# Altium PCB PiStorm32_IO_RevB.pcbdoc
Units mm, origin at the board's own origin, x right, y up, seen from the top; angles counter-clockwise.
Board outline 55 x 107.5 mm, 2 copper layers (Top Layer, Bottom Layer), stack 1.569 mm thick; 30 components, 37 nets, 213 pads, 281 vias.
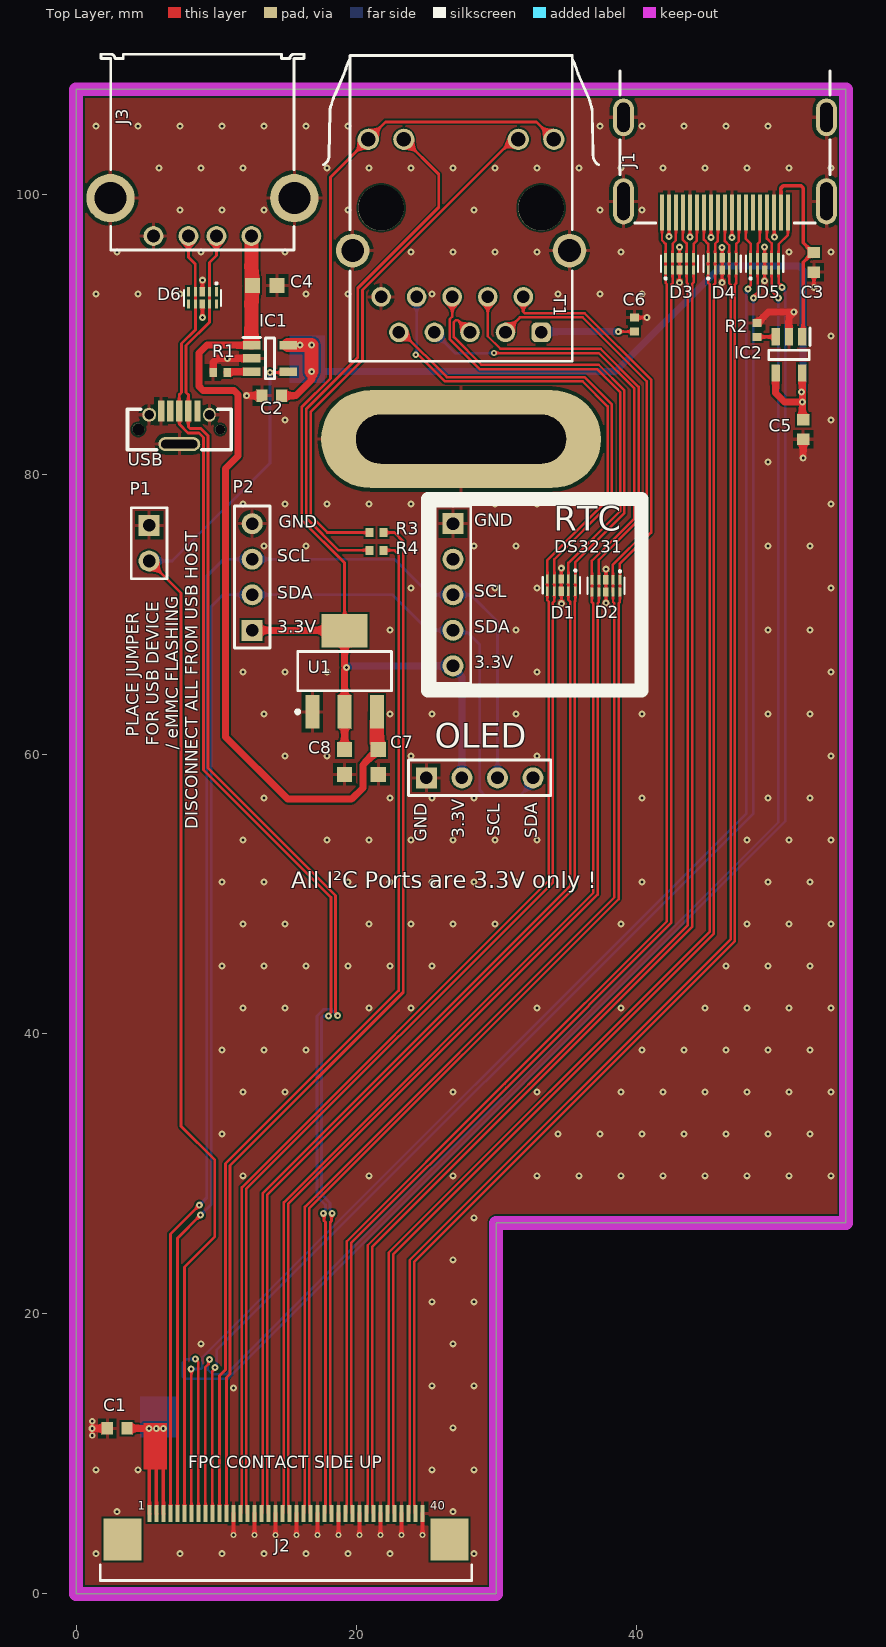
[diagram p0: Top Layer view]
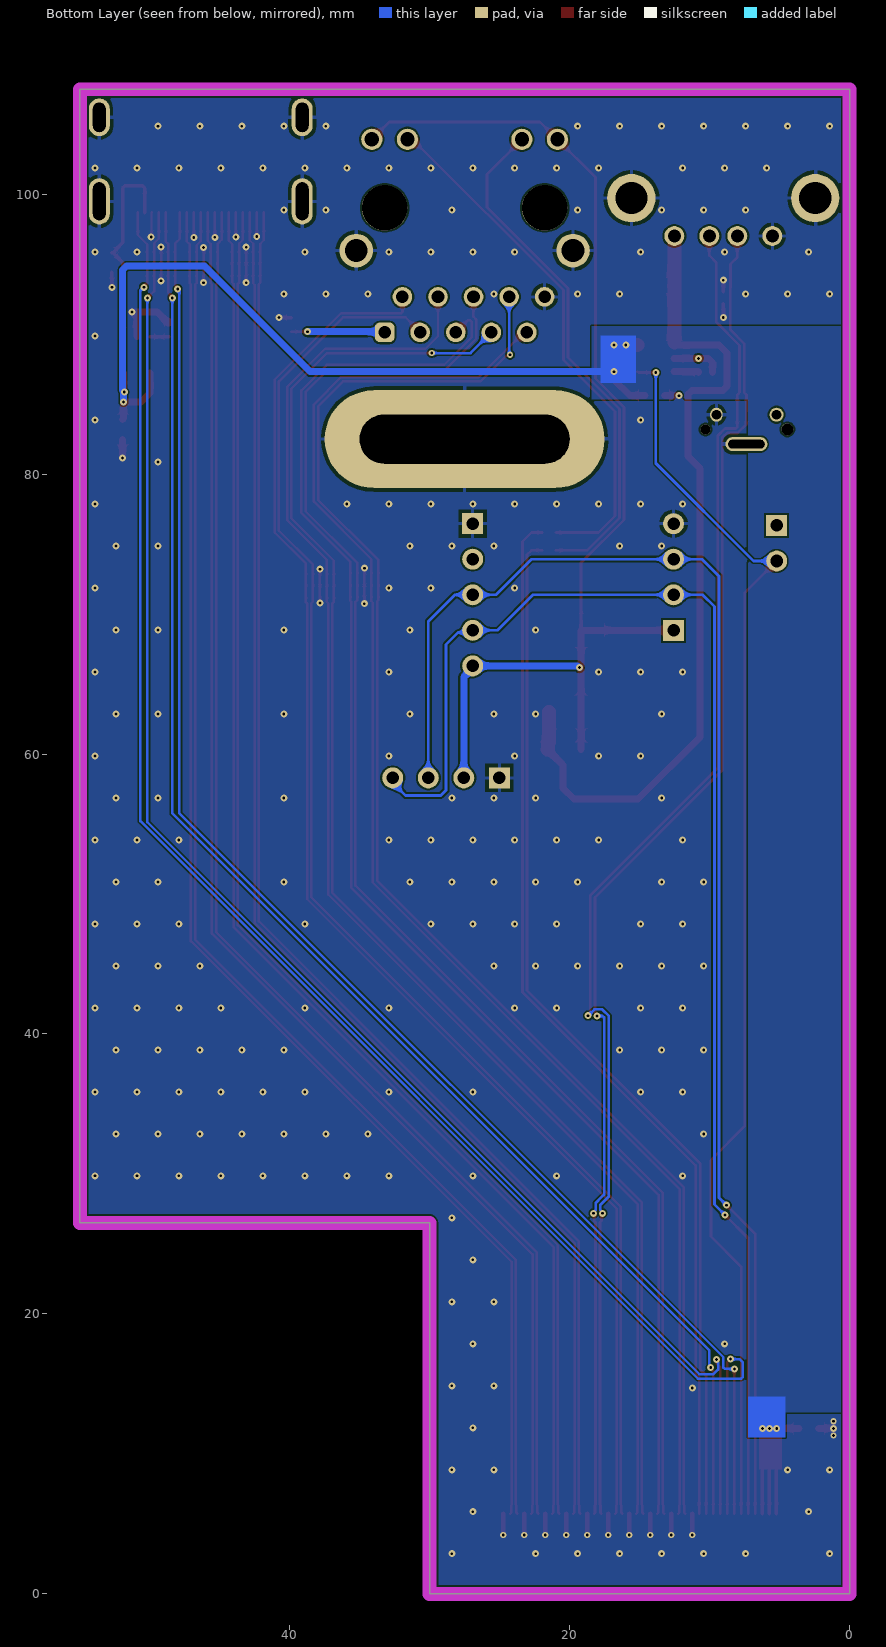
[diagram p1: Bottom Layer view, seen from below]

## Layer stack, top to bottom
Top Solder: solder mask 0.0254, SM-001, Dk 4
Top Layer: signal copper 0.035
Dielectric 1: core 1.4986, Core-043, Dk 4.3
Bottom Layer: signal copper 0.035
Bottom Solder: solder mask 0.0254, SM-001, Dk 4

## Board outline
0,0 0,107.5 55,107.5 55,26.5 30,26.5 30,0

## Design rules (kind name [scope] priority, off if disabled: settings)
Clearance [All] p1: gap=0.127 ignorepadtopadclearanceinfootprint=FALSE
DiffPairsRouting [All] p1: maxlimit=0.254 minlimit=0.127 mostfreqgap=0.127 toplayer_minwidth=0.127 toplayer_maxwidth=0.381 toplayer_prefwidth=0.127 bottomlayer_minwidth=0.127 bottomlayer_maxwidth=0.381 bottomlayer_prefwidth=0.127 maxuncoupledlength=12.7
PolygonConnect [All] p1: thpad.connectstyle=Relief thpad.reliefconductorwidth=0.254 thpad.reliefentries=4 thpad.polygonreliefangle="90 Angle" thpad.airgapwidth=0.254 smdpad.connectstyle=Relief smdpad.reliefconductorwidth=0.254 smdpad.reliefentries=4 smdpad.polygonreliefangle="90 Angle" smdpad.airgapwidth=0.254 via.connectstyle=Direct via.reliefconductorwidth=0.254 via.reliefentries=4 via.polygonreliefangle="90 Angle" via.airgapwidth=0.254
RoutingVias [All] p1: holewidth=0.2 width=0.5 viastyle="Through Hole" minholewidth=0.2 minwidth=0.5 maxholewidth=0.6 maxwidth=1
SolderMaskExpansion [All] p1: expansion=0.102 istentingtop=FALSE
UnRoutedNet [All] p1: checkbadconnections=TRUE
Width [All] p1: maxlimit=4 minlimit=0.178 preferedwidth=0.254
28 further rules are at their usual default settings.

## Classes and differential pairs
differential pair USB: +USB_P -USB_N
differential pair HDMI_TX2: +HDMI_TX2_P -HDMI_TX2_N
differential pair HDMI_TX1: +HDMI_TX1_P -HDMI_TX1_N
differential pair HDMI_TX0: +HDMI_TX0_P -HDMI_TX0_N
differential pair HDMI_CLK: +HDMI_CLK_P -HDMI_CLK_N
differential pair ETH_P3: +ETH_P3_P -ETH_P3_N
differential pair ETH_P2: +ETH_P2_P -ETH_P2_N
differential pair ETH_P1: +ETH_P1_P -ETH_P1_N
differential pair ETH_P0: +ETH_P0_P -ETH_P0_N

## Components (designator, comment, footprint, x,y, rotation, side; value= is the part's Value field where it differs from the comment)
C1 "Cap Semi" 1608[0603] 2.921,11.818 r180 top value=2u2
C2 "Cap Semi" 1608[0603] 13.97,85.605 r180 top value=2u2
C3 "Cap Semi" 1608[0603] 52.705,95.13 r270 top value=2u2
C4 "Cap Semi" RCL_C0603K 13.462,93.479 r0 top value=22uf/0603
C5 "Cap Semi" 1608[0603] 51.943,83.192 r270 top value=2u2
C6 "100nf/0402" 005-00008 39.878,90.685 r270 top value=1uF
C7 "Cap Semi" RCL_C0603K 21.59,59.443 r270 top value=22uf/0603
C8 "Cap Semi" RCL_C0603K 19.177,59.443 r270 top value=22uf/0603
D1 "ESD5304D-TP" DFN2510-10_L2.5-W1.0-P0.50-BL 34.663,72.068 r180 top
D2 "ESD5304D-TP" DFN2510-10_L2.5-W1.0-P0.50-BL 37.846,72.016 r180 top
D3 "ESD5304D-TP" DFN2510-10_L2.5-W1.0-P0.50-BL 43.108,95.023 r0 top
D4 "ESD5304D-TP" DFN2510-10_L2.5-W1.0-P0.50-BL 46.156,95.023 r0 top
D5 "ESD5304D-TP" DFN2510-10_L2.5-W1.0-P0.50-BL 49.188,95.023 r0 top
D6 "ESD5304D-TP" DFN2510-10_L2.5-W1.0-P0.50-BL 9.017,92.59 r180 top
IC1 "MT9700" SOT95P280X135-5N 13.843,88.272 r0 top
IC2 "MT9700" SOT95P280X135-5N 50.927,88.526 r270 top
J1 "C138388" 685119134923 46.355,104.02 r180 top
J2 "68714014022" 68714014022 14.986,3.175 r0 top
J3 "C112456" 61400416021 9.017,103.004 r180 top
OLED "Header 4" HDR1X4 25.019,58.3 r0 top
P1 "Header 2" HDR1X2 5.207,76.334 r270 top
P2 "Header 4" HDR1X4 12.573,68.841 r90 top
R1 "5.6k" 005-00008 10.287,87.256 r0 top value=22
R2 "12k" 005-00008 48.641,90.304 r270 top value=22
R3 "470" 005-00008 21.463,75.826 r180 top value=22
R4 "470" 005-00008 21.463,74.556 r180 top value=22
RTC "Header 5" HDR1X5 26.924,76.461 r270 top
T1 "HY911130A" HY911130A 27.5,99.021 r0 top
U1 "LM1117IMPX-3.3" MP04A_N 19.177,65.92 r90 top
USB "U-E-051N-4BH21-F1B" MICRO-USB-SMD_U-E-051N-4BH21-F1B 7.366,83.319 r180 top

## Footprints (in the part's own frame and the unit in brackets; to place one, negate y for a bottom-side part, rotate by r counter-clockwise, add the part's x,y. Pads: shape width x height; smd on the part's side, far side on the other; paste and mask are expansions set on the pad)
005-00008 [mm] "1005, EIA 0402, Chip Capacitor, 2-Leads, Body 1.00x0.50mm, IPC High Density"
  rect 0.55x0.65 smd: 1(-0.5,0) 2(0.5,0)
  body extent -0.52,-0.27 0.53,0.28, height 0.4
1608[0603] [mm] "Chip Capacitor, Body 1.6x0.8mm, IPC High Density"
  rect 0.8x0.9 smd: 1(-0.7,0) 2(0.7,0)
  body extent -0.87,-0.48 0.87,0.48, height 1.3
61400416021 [mm] "USB 2.0 Type A Horizontal"
  round 1.42 hole 0.92: 1(-3.5,5.99) 2(-1,5.99) 3(1,5.99) 4(3.5,5.99)
  round 3.45 hole 2.3: Shell(-6.57,3.28) Shell(6.57,3.28)
  silkscreen extent -7.25,-7 7.25,7, body extent -8,-7 8,7, height 7.63
68714014022 [mm] "ZIF Connectors, Horizontal, Top Contact, pitch 0.5mm, 40p"
  rect 0.3x1.2 smd: 1(-9.75,2.56) 2(-9.25,2.56) 3(-8.75,2.56) 4(-8.25,2.56) 5(-7.75,2.56) 6(-7.25,2.56) 7(-6.75,2.56) 8(-6.25,2.56) 9(-5.75,2.56) 10(-5.25,2.56) 11(-4.75,2.56) 12(-4.25,2.56) 13(-3.75,2.56) 14(-3.25,2.56) 15(-2.75,2.56) 16(-2.25,2.56) 17(-1.75,2.56) 18(-1.25,2.56) 19(-0.75,2.56) 20(-0.25,2.56) 21(0.25,2.56) 22(0.75,2.56) 23(1.25,2.56) 24(1.75,2.56) 25(2.25,2.56) 26(2.75,2.56) 27(3.25,2.56) 28(3.75,2.56) 29(4.25,2.56) 30(4.75,2.56) 31(5.25,2.56) 32(5.75,2.56) 33(6.25,2.56) 34(6.75,2.56) 35(7.25,2.56) 36(7.75,2.56) 37(8.25,2.56) 38(8.75,2.56) 39(9.25,2.56) 40(9.75,2.56)
  rect 2.7x3 smd: MP1(-11.68,0.7) MP2(11.68,0.7)
  silkscreen extent -13.27,-2.23 13.28,-1.1, body extent -13.2,-2.15 13.2,2.95, height 2.1
685119134923 [mm] "HDMI SMT Horizontal"
  rect 0.28x2.6 smd: 1(4.5,5.325) 2(4,5.325) 3(3.5,5.325) 4(3,5.325) 5(2.5,5.325) 6(2,5.325) 7(1.5,5.325) 8(1,5.325) 9(0.5,5.325) 10(0,5.325) 11(-0.5,5.325) 12(-1,5.325) 13(-1.5,5.325) 14(-2,5.325) 15(-2.5,5.325) 16(-3,5.325) 17(-3.5,5.325) 18(-4,5.325) 19(-4.5,5.325)
  oval 1.5x3.3 hole 0.9 slot 2.7 at 90 deg: Shell(-7.25,4.525) Shell(7.25,4.525)
  oval 1.5x2.7 hole 0.9 slot 2.1 at 90 deg: Shell(-7.25,-1.475) Shell(7.25,-1.475)
  silkscreen extent -7.5,-4.78 7.5,6.08, body extent -7.55,-6.07 7.45,6.08, height 6.17
DFN2510-10_L2.5-W1.0-P0.50-BL [mm]
  rect 0.2x0.665 smd: 1(-1,-0.433) 2(-0.5,-0.433) 4(0.5,-0.433) 5(1,-0.433) 6(1,0.433) 7(0.5,0.433) 9(-0.5,0.433) 10(-1,0.433)
  rect 0.4x0.665 smd: 3(0,-0.433) 8(0,0.433)
  silkscreen extent -1.33,-1.11 1.33,0.58
HDR1X2 [mm] "Connector; Header; 2 Position"
  rect 1.5x1.5 hole 0.9: 1(0,0)
  round 1.5 hole 0.9: 2(2.54,0)
  silkscreen extent -1.27,-1.27 3.81,1.27
HDR1X4 [mm] "Connector; Header; 4 Position"
  rect 1.5x1.5 hole 0.9: 1(0,0)
  round 1.5 hole 0.9: 2(2.54,0) 3(5.08,0) 4(7.62,0)
  silkscreen extent -1.27,-1.27 8.89,1.27
HDR1X5 [mm] "Connector; Header; 5 Position"
  rect 1.5x1.5 hole 0.9: 1(0,0)
  round 1.5 hole 0.9: 2(2.54,0) 3(5.08,0) 4(7.62,0) 5(10.16,0)
  silkscreen extent -1.27,-1.27 11.43,1.27
HY911130A [mm] "LAN Transformer, body 21.84x15.88mm"
  rrect50% 1.4x1.4 hole 0.9: 1(5.715,-8.89)
  round 1.4 hole 0.9: 2(4.445,-6.35) 3(3.175,-8.89) 4(1.905,-6.35) 5(0.635,-8.89) 6(-0.635,-6.35) 7(-1.905,-8.89) 8(-3.175,-6.35) 9(-4.445,-8.89) 10(-5.715,-6.35)
  round 1.52 hole 1.02: 11(6.63,4.9) 12(4.09,4.9) 13(-4.09,4.9) 14(-6.63,4.9)
  round 3.25 hole 3.25 unplated: MH1(5.715,0) MH2(-5.715,0)
  round 2.4 hole 1.63: Shell(-7.745,-3.05) Shell(7.745,-3.05)
  silkscreen extent -9.83,-10.95 9.83,10.89, body extent -9.92,-10.95 9.92,10.89, height 16.01
MICRO-USB-SMD_U-E-051N-4BH21-F1B [mm]
  rect 0.45x1.5 smd: 1(-1.3,-1.175) 2(-0.65,-1.175) 3(0,-1.175) 4(0.65,-1.175) 5(1.3,-1.175)
  oval 0.9x1 hole 0.7: 6(-2.15,-0.925)
  round 1 hole 0.7: 7(2.15,-0.925)
  oval 3x1 hole 0.6 slot 2.6 at 0 deg: 8(0,1.175)
  round 0.7 hole 0.7 unplated: ""(-2.925,0.125)
  round 0.85 hole 0.85 unplated: ""(2.925,0.125)
  silkscreen extent -3.7,-1.33 3.7,1.57
MP04A_N [mm] "SOT223, 4-Leads, Body 6.5x3.5mm, Pitch 2.3mm, Lead Span 7mm, IPC Medium Density"
  rect 2.4x1 smd: 1(-2.9,2.3) 2(-2.9,0) 3(-2.9,-2.3)
  rect 2.4x3.3 smd: 4(2.9,0)
  silkscreen extent -3.02,-3.35 1.4,3.47, body extent -1.85,-3.35 1.85,3.35, height 1.8
RCL_C0603K [mil]
  rect 42x43 smd: 1(-34.45,0) 2(35,0)
SOT95P280X135-5N [mm]
  rect 1.25x0.6 smd: 1(-1.3,0.95) 2(-1.3,0) 3(-1.3,-0.95) 4(1.3,-0.95) 5(1.3,0.95)
  silkscreen extent -1.92,-1.45 0.33,1.5, body extent -1.4,-1.45 1.4,1.45, height 1.35

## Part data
C1 C2 C3 C4 C5 C7 C8: "Capacitor (Semiconductor SIM Model)"
C6: library part 004-00003, "Capacitor 1uF 10V Ceramic 10% 0402", Manufacturer1=AVX, Manufacturer1 Part Number=0402ZD105KAT2A, Package="1005, EIA 0402, Chip Capacitor, 2-Leads, Body 1.00x0.50mm, IPC High Density", Part Number=011-00010, Voltage=10V
D1 D2 D3 D4 D5 D6: BOM_JLCPCB Part Class="Extended Part", BOM_Manufacturer="TECH PUBLIC(台舟)"
IC1 IC2: "Integrated Circuit", Manufacturer_Name=Aerosemi
J1: library part 685119134923, "HDMI Type A Receptacle WR-HDMI, Horizontal, SMT", Contact Resistance="30 mOhm", Operating Temperature="-20 to 85 degC", Rated Current="0.5 A", Working Voltage="40 VDC"
J2: "WR-FPC SMT ZIF Horizontal Top Contact, pitch 0.5mm, 40p", Contact Resistance=20mOhm, Manufacturer="Wurth Elektronik", Operating Temperature="-25 to +85degC", Rated Current=0.5A, Working Voltage=50VAC
J3: library part 61400416021, "USB 2.0 Type A, Receptacle, Horizontal, THT", Manufacturer="Wurth Elektronik", Operating Temperature="-40 to +105degC", Rated Current=1.5A, Working Voltage=30VAC
OLED P2: "Header, 4-Pin"
P1: "Header, 2-Pin"
R1 R2 R3 R4: library part 004-00008, "RES 22 OHM 1/16W 5% 0402", Manufacturer1="Stackpole Electronics", Manufacturer1 Part Number=RMCF0402JT22R0, Package="1005, EIA 0402, Chip Resistor, 2-Leads, Body 1.00x0.50mm, IPC High Density", Part Number=009-00020, Power=1/16W, Tolerance=0.05
RTC: "Header, 5-Pin"
T1: "LAN Transformer, THT, 10/100/1000 Base-T, Port 1x1, Tab Down", Manufacturer="Wurth Elektronik", Manufacturer Part Number=7499111446, Operating Temperature="-40 to +85degC"
U1: "800mA Low-Dropout Linear Regulator, 4-pin SOT-223", Manufacturer="National Semiconductor", PackageTopMarking=XYTT*N05B, PowerWise=N
USB: BOM_JLCPCB Part Class="Extended Part", BOM_Manufacturer="XKB Enterprise"

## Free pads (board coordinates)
  oval 20x7 hole 3.5 slot 15 at 0 deg: MNT(27.5,82.5)

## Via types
v1: diameter 0.5, hole 0.2, Top Layer to Bottom Layer, tented both sides, 267 vias
v2: diameter 0.45, hole 0.2, Top Layer to Bottom Layer, tented both sides, 14 vias

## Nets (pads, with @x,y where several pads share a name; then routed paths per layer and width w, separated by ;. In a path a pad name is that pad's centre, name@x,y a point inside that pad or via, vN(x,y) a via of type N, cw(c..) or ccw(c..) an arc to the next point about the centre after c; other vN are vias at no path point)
+5: C1.1 C2.1 C5.1 IC1.5 IC2.4 IC2.5 J2.1 J2.2 J2.3 | length 81.6
  Top Layer w0.254: J2.1 5.222,5.75 5.222,11.803 v1(5.207,11.818) v1@5.236,11.847 ; v1(5.723,11.818) 5.73,11.811 5.73,5.742 J2.2 ; v1(6.223,11.818) 6.23,11.811 6.23,5.742 J2.3
  Top Layer w0.5: C1.1 v1(5.207,11.818) ; C2.1@14.608,85.605 15.691,85.605 16.825,86.739 v1(16.825,87.322) ; IC2.4 49.977,85.798 50.617,85.158 v1(51.877,85.158) ; IC2.5 51.877,85.92 v1(51.816,85.859) 51.877,85.798 v1(51.877,85.158) ; C5.1 51.877,83.958 v1(51.877,85.158)
  Top Layer w1: IC1.5 v1(15.984,89.222) v1(16.825,89.222) v1(16.825,87.322)
  Bottom Layer w0.5: v1(16.825,87.322) 38.547,87.322 46.101,94.876 51.65,94.876 51.943,94.583 51.943,85.986 v1(51.816,85.859) 51.877,85.798 v1(51.877,85.158)
+5_SW: C4.1 C7.1 IC1.1 J3.1 U1.3 | length 59.8
  Top Layer w0.5: IC1.1 9.332,89.222 8.763,88.653 8.763,86.279 9.056,85.986 11.264,85.986 11.557,85.693 11.557,81.287 10.668,80.398 10.668,61.221 15.113,56.776 19.685,56.776 20.489,57.58 20.489,59.23 21.577,60.318 C7.1
  Top Layer w1: IC1.1@12.517,89.422 12.517,93.396 12.554,93.433 C4.1@12.554,93.479 ; C4.1@12.517,93.479 J3.1 ; U1.3 21.477,62.32 21.463,62.306 21.463,60.817 21.544,60.736 21.544,60.351 C7.1@21.577,60.318
ETH_LNK: J2.12 R3.1 | length 76.4
  Top Layer w0.2: J2.12 10.736,15.442 10.995,15.701 10.995,30.606 23.368,42.979 23.368,75.191 22.733,75.826 R3.1
ETH_P0_N: D2.2 D2.9 J2.23 T1.3 | length 103.5
  Top Layer w0.178: J2.23 16.297,5.796 16.297,6.314 16.334,6.35 16.334,27.644 38.444,49.754 38.444,70.776 38.354,70.866 D2.9@38.354,71.538 ; T1.3@30.675,90.161 31.707,91.193 36.195,91.193 40.767,86.621 40.767,75.953 38.346,73.532 D2.2 D2.9
ETH_P0_P: D2.1 D2.10 J2.24 T1.2 | length 103.4
  Top Layer w0.178: J2.24 16.675,5.796 16.675,6.314 16.638,6.35 16.638,27.517 38.748,49.627 38.748,70.759 38.846,70.857 D2.1 38.846,73.601 41.072,75.827 41.072,86.747 36.321,91.498 32.045,91.498 31.94,91.602 T1.2@31.94,92.696
ETH_P1_N: D2.4 D2.7 J2.21 T1.4 | length 106
  Top Layer w0.178: J2.21 15.175,5.796 15.175,6.314 15.138,6.35 15.138,27.845 37.248,49.955 37.248,70.776 37.346,70.874 D2.7 D2.4 37.338,72.457 37.338,73.871 40.183,76.716 40.183,86.239 37.464,88.958 30.553,88.958 30.302,88.958 29.405,89.855 T1.4
ETH_P1_P: D2.5 D2.6 J2.20 T1.7 | length 106.8
  Top Layer w0.178: J2.20 14.797,5.796 14.797,6.314 14.834,6.35 14.834,27.972 36.944,50.082 36.944,70.759 36.846,70.857 D2.6 D2.5 36.846,73.81 39.878,76.842 39.878,86.113 37.338,88.653 30.427,88.653 v2(29.845,88.653)
  Bottom Layer w0.178: T1.7 27.073,88.653 v2(29.845,88.653)
ETH_P2_N: D1.2 D1.9 J2.17 T1.6 | length 107.6
  Top Layer w0.178: J2.17 13.297,5.796 13.297,6.314 13.334,6.35 13.334,28.631 35.305,50.602 35.305,70.874 35.163,71.016 D1.9 ; T1.6 26.87,92.666 26.87,91.249 26.676,91.056 26.676,89.664 28.83,87.51 37.211,87.51 38.862,85.859 38.862,77.35 35.163,73.651 D1.2 ; D1.9@35.163,71.724 D1.2
ETH_P2_P: D1.1 D1.10 J2.18 T1.5 | length 107.3
  Top Layer w0.178: J2.18 13.675,5.796 13.675,6.314 13.638,6.35 13.638,28.504 35.61,50.476 35.61,70.891 35.663,70.944 D1.10 D1.1 35.663,73.72 39.167,77.224 39.167,85.985 37.337,87.815 28.956,87.815 26.981,89.79 26.981,90.869 27.115,91.003 27.263,91.003 T1.5
ETH_P3_N: D1.4 D1.7 J2.15 T1.9 | length 107.5
  Top Layer w0.178: J2.15 12.175,5.796 12.175,6.314 12.138,6.35 12.138,28.909 34.065,50.836 34.065,70.828 34.163,70.926 D1.7 D1.4 34.163,73.921 38.278,78.036 38.278,84.969 36.321,86.926 26.481,86.926 23.276,90.131 T1.9
ETH_P3_P: D1.5 D1.6 J2.14 T1.8 | length 109.5
  Top Layer w0.178: J2.14 11.797,5.796 11.797,6.314 11.834,6.35 11.834,29.036 33.761,50.963 33.761,70.894 33.663,70.992 D1.6 D1.5 33.663,73.852 37.973,78.162 37.973,84.843 36.195,86.621 26.354,86.621 24.502,88.474 24.309,88.474 v2(24.257,88.526)
  Bottom Layer w0.178: v2(24.257,88.526) 24.257,88.6 24.325,88.668 T1.8
ETH_SPD: J2.11 R4.1 | length 75
  Top Layer w0.2: J2.11 10.236,15.577 10.668,16.009 10.668,30.741 23.041,43.114 23.041,74.248 22.733,74.556 R4.1
GND: C1.2 C2.2 C3.2 C4.2 C5.2 C6.1 C7.2 C8.2 D1.3 D1.8 D2.3 D2.8 D3.3 D3.8 D4.3 D4.8 D5.3 D5.8 D6.3 D6.8 IC1.2 IC2.2 J1.2 J1.5 J1.8 J1.11 J1.17 J1.Shell J2.13 J2.16 J2.19 J2.22 J2.25 J2.28 J2.31 J2.34 J2.37 J2.40 J3.4 J3.Shell OLED.1 P1.1 P2.4 pad.MNT R1.1 R2.1 RTC.1 T1.10 T1.Shell U1.1 USB.5 USB.6 USB.7 USB.8 | length 53.3
  Top Layer w0.178: v1(34.671,70.746) 34.663,70.754 D1.8 v1(34.663,73.278) v1@34.671,73.286 ; v1(37.846,70.798) D2.8 D2.3 v1(37.846,73.211) ; v1(42.355,96.972) J1.2 ; v1(43.108,93.678) D3.8 v1(43.108,96.218) ; v1(43.855,96.948) J1.5 ; v1(45.355,96.924) J1.8 ; v1(46.153,96.198) 46.154,96.196 46.154,95.458 D4.8 v1(46.156,93.678) ; v1(46.855,96.916) J1.11 ; v1(49.188,96.234) D5.8 D5.3 49.188,93.821 v1(49.196,93.813) v1@49.204,93.805 ; J1.17 49.875,98.675 49.875,96.968 v1(49.895,96.948)
  Top Layer w0.254: v1(9.017,91.193) D6.8 ; D6.3 v1(9.017,93.86) ; C6.1 40.759,91.185 v1(40.767,91.193) ; v1(52.705,93.352) C3.2
  Top Layer w0.3: v2(1.143,11.31) v2(1.143,12.326) ; v2(11.236,4.198) J2.13 ; v2(12.736,4.198) J2.16 ; v2(14.236,4.198) J2.19 ; v2(15.736,4.198) J2.22 ; v2(17.236,4.198) J2.25 ; v2(18.736,4.198) J2.28 ; v2(20.236,4.198) J2.31 ; v2(21.736,4.198) J2.34 ; v2(23.236,4.198) J2.37 ; v2(24.736,4.198) J2.40
  Top Layer w0.5: v1(1.143,11.818) C1.2 ; R1.1 9.787,87.979 10.08,88.272 v1(10.795,88.272) IC1.2 ; v1(12.184,85.605) C2.2@13.208,85.605 ; R2.1 48.691,90.804 49.461,91.574 v1(51.275,91.574) 51.308,91.574 50.927,91.193 IC2.2 ; v1(51.943,81.16) C5.2
  other v1: 1.421,2.863 7.421,2.863 10.421,2.863 13.421,2.863 16.421,2.863 19.421,2.863 22.421,2.863 28.421,2.863 2.921,5.863 26.921,5.863 1.421,8.863 4.421,8.863 25.421,8.863 28.421,8.863 26.921,11.863 11.236,14.705 25.421,14.863 28.421,14.863 8.921,17.863 26.921,17.863 25.421,20.863 28.421,20.863 26.921,23.863 28.421,26.863 11.921,29.863 20.921,29.863 26.921,29.863 32.921,29.863 35.921,29.863 38.921,29.863 41.921,29.863 44.921,29.863 47.921,29.863 50.921,29.863 53.921,29.863 10.421,32.863 34.421,32.863 37.421,32.863 40.421,32.863 43.421,32.863 46.421,32.863 49.421,32.863 52.421,32.863 11.921,35.863 14.921,35.863 26.921,35.863 32.921,35.863 38.921,35.863 41.921,35.863 44.921,35.863 47.921,35.863 50.921,35.863 53.921,35.863 10.421,38.863 13.421,38.863 16.421,38.863 40.421,38.863 43.421,38.863 46.421,38.863 49.421,38.863 52.421,38.863 11.921,41.863 14.921,41.863 20.921,41.863 23.921,41.863 32.921,41.863 38.921,41.863 44.921,41.863 47.921,41.863 50.921,41.863 53.921,41.863 10.421,44.863 13.421,44.863 16.421,44.863 19.421,44.863 22.421,44.863 25.421,44.863 46.421,44.863 49.421,44.863 52.421,44.863 11.921,47.863 14.921,47.863 20.921,47.863 23.921,47.863 26.921,47.863 29.921,47.863 38.921,47.863 47.921,47.863 50.921,47.863 53.921,47.863 10.421,50.863 13.421,50.863 19.421,50.863 22.421,50.863 25.421,50.863 28.421,50.863 31.421,50.863 40.421,50.863 49.421,50.863 52.421,50.863 11.921,53.863 17.921,53.863 20.921,53.863 23.921,53.863 26.921,53.863 29.921,53.863 32.921,53.863 47.921,53.863 50.921,53.863 53.921,53.863 13.421,56.863 22.421,56.863 25.421,56.863 28.421,56.863 40.421,56.863 49.421,56.863 52.421,56.863 14.921,59.863 17.921,59.863 23.921,59.863 32.921,59.863 53.921,59.863 13.421,62.863 22.421,62.863 25.421,62.863 31.421,62.863 40.421,62.863 49.421,62.863 52.421,62.863 11.921,65.863 14.921,65.863 17.921,65.863 32.921,65.863 53.921,65.863 22.421,68.863 31.421,68.863 40.421,68.863 49.421,68.863 52.421,68.863 23.921,71.863 29.921,71.863 32.921,71.863 53.921,71.863 13.421,74.863 16.421,74.863 25.421,74.863 28.421,74.863 31.421,74.863 49.421,74.863 52.421,74.863 11.921,77.863 14.921,77.863 17.921,77.863 20.921,77.863 23.921,77.863 26.921,77.863 29.921,77.863 32.921,77.863 35.921,77.863 53.921,77.863 49.421,80.863 14.921,83.863 53.921,83.863 53.921,89.863 1.421,92.863 4.421,92.863 7.421,92.863 16.421,92.863 19.421,92.863 25.421,92.863 34.421,92.863 37.421,92.863 40.421,92.863 2.921,95.863 8.921,95.863 14.921,95.863 23.921,95.863 26.921,95.863 29.921,95.863 32.921,95.863 38.921,95.863 50.921,95.863 53.921,95.863 7.421,98.863 10.421,98.863 13.421,98.863 19.421,98.863 28.421,98.863 37.421,98.863 40.421,98.863 5.921,101.863 8.921,101.863 11.921,101.863 17.921,101.863 20.921,101.863 23.921,101.863 26.921,101.863 29.921,101.863 32.921,101.863 35.921,101.863 38.921,101.863 41.921,101.863 44.921,101.863 47.921,101.863 50.921,101.863 53.921,101.863 1.421,104.863 4.421,104.863 7.421,104.863 10.421,104.863 13.421,104.863 16.421,104.863 19.421,104.863 37.421,104.863 40.421,104.863 43.421,104.863 46.421,104.863 49.421,104.863
HDMI_CEC: D5.1 D5.10 J1.13 J2.7 | length 110.1
  Top Layer w0.178: v1(8.213,16.062) 8.236,16.039 J2.7 ; J1.13 47.855,96.805 48.188,96.472 D5.10 D5.1 48.188,93.481 48.006,93.299 v1(48.006,93.225)
  Bottom Layer w0.178: v1(8.213,16.062) 8.913,16.062 9.017,16.166 9.017,16.898 47.879,55.76 47.879,93.024 48.006,93.151 v1(48.006,93.225)
HDMI_CLK_N: D4.5 D4.6 J1.12 J2.39 | length 102.9
  Top Layer w0.178: J2.39 24.175,5.796 24.175,6.314 24.138,6.35 24.138,23.714 47.058,46.634 47.058,93.547 47.156,93.645 D4.5 47.145,94.579 D4.5@47.145,94.308 ; D4.5@47.156,94.601 D4.6 47.156,96.439 47.355,96.638 J1.12
HDMI_CLK_P: D4.4 D4.7 J1.10 J2.38 | length 102.7
  Top Layer w0.178: J2.38 23.797,5.796 23.797,6.314 23.834,6.35 23.834,23.841 46.754,46.761 46.754,93.543 46.656,93.64 D4.4 46.656,96.353 46.355,96.654 J1.10
HDMI_HPD: D5.5 D5.6 J1.19 J2.8 | length 116.7
  Top Layer w0.178: v1(8.509,16.771) 8.736,16.544 J2.8 ; v1(50.419,93.352) 50.419,93.426 50.188,93.657 D5.6 50.188,96.423 50.855,97.09 J1.19
  Bottom Layer w0.178: v1(8.509,16.771) 7.874,16.771 7.62,16.517 7.62,15.501 7.747,15.374 10.845,15.374 50.673,55.202 50.673,93.098 v1(50.419,93.352)
HDMI_SCL: D5.2 D5.9 J1.15 J2.10 | length 109.2
  Top Layer w0.178: J2.10 9.736,15.896 9.924,16.083 v1(9.924,16.161) ; v1(48.387,92.59) 48.387,92.664 48.688,92.965 D5.2 D5.9 48.688,96.447 48.855,96.614 J1.15
  Bottom Layer w0.178: v1(9.924,16.161) 9.985,16.223 9.985,16.379 10.033,16.426 10.033,17.406 48.387,55.76 v1(48.387,92.59)
HDMI_SDA: D5.4 D5.7 J1.16 J2.9 | length 113
  Top Layer w0.178: J2.9 9.236,16.19 9.454,16.409 9.454,16.676 v1(9.516,16.738) ; J1.16 49.355,96.829 49.688,96.496 D5.7 D5.4 49.688,93.067 v1(50.165,92.59)
  Bottom Layer w0.178: v1(9.516,16.738) 9.516,16.651 9.421,16.556 9.421,16.529 9.398,16.506 9.398,16.02 9.723,15.695 10.735,15.695 50.165,55.125 v1(50.165,92.59)
HDMI_TX0_N: D4.2 D4.9 J1.9 J2.36 | length 102.6
  Top Layer w0.178: J2.36 22.675,5.796 22.675,6.314 22.638,6.35 22.638,24.246 45.558,47.166 45.558,93.542 45.656,93.64 D4.2 D4.9 45.656,96.463 45.855,96.662 J1.9
HDMI_TX0_P: D4.1 D4.10 J1.7 J2.35 | length 102.7
  Top Layer w0.178: J2.35 22.297,5.796 22.297,6.314 22.334,6.35 22.334,24.373 45.254,47.293 45.254,93.564 45.156,93.662 D4.1 D4.10 45.156,96.456 44.855,96.757 J1.7
HDMI_TX1_N: D3.5 D3.6 J1.6 J2.33 | length 102.9
  Top Layer w0.178: J2.33 21.175,5.796 21.175,6.314 21.138,6.35 21.138,24.778 44.01,47.65 44.01,93.596 44.108,93.694 D3.5 ; D3.5@44.097,94.347 44.097,94.59 44.108,94.601 D3.6 44.108,96.439 44.355,96.686 J1.6
HDMI_TX1_P: D3.4 D3.7 J1.4 J2.32 | length 102.6
  Top Layer w0.178: J2.32 20.797,5.796 20.797,6.314 20.834,6.35 20.834,24.905 43.706,47.777 43.706,93.588 43.608,93.686 D3.4 D3.7 43.608,96.48 43.355,96.733 J1.4
HDMI_TX2_N: D3.2 D3.9 J1.3 J2.30 | length 102.6
  Top Layer w0.178: J2.30 19.675,5.796 19.675,6.314 19.638,6.35 19.638,25.056 30.733,36.151 42.51,47.928 42.51,93.543 42.608,93.64 D3.2 ; D3.2@42.597,94.59 42.597,95.139 42.597,95.445 D3.9 42.608,96.463 42.855,96.71 J1.3
HDMI_TX2_P: D3.1 D3.10 J1.1 J2.29 | length 102.6
  Top Layer w0.178: J2.29 19.297,5.796 19.297,6.314 19.334,6.35 19.334,25.183 30.607,36.456 42.206,48.055 42.206,93.564 42.108,93.662 D3.1 D3.10 42.108,96.456 41.855,96.709 J1.1
NetC3_1: C3.1 IC2.1 J1.18 | length 14.7
  Top Layer w0.254: J1.18 50.355,100.442 50.504,100.591 51.794,100.591 51.943,100.442 51.943,96.527 52.367,96.103 52.382,96.103 52.513,95.972 C3.1@52.513,95.83 ; IC2.1 51.943,89.892 51.943,95.13 52.37,95.557 52.382,95.557 52.578,95.753 52.578,95.765 52.643,95.83 C3.1
NetC6_2: C6.2 T1.1 | length 6.7
  Top Layer w0.178: v1(38.735,90.177) 38.743,90.185 C6.2
  Bottom Layer w0.178: T1.1@33.215,90.161 T1.1@33.231,90.177
  Bottom Layer w0.5: T1.1@33.231,90.177 v1(38.735,90.177)
NetIC1_3: IC1.3 R1.2 | length 1.8
  Top Layer w0.5: R1.2 10.787,87.297 10.812,87.322 IC1.3
NetIC2_3: IC2.3 R2.2 | length 1.3
  Top Layer w0.254: R2.2 49.955,89.804 IC2.3
NetR3_2: R3.2 T1.12 | length 37.7
  Top Layer w0.2: R3.2 17.943,75.826 16.764,77.005 16.764,84.462 20.447,88.145 20.447,93.144 T1.12@31.323,104.02
NetR4_2: R4.2 T1.13 | length 37.5
  Top Layer w0.2: R4.2 18.75,74.556 16.437,76.869 16.437,84.643 20.12,88.326 20.12,93.279 25.908,99.067 25.908,101.423 T1.13
SCL: J2.4 OLED.3 P2.3 RTC.3 | length 102.3
  Top Layer w0.2: J2.4 6.736,25.706 v1(8.798,27.768)
  Bottom Layer w0.2: v1(8.798,27.768) 9.325,28.295 9.325,50.095 9.325,72.705 10.541,73.921 P2.3 22.733,73.921 25.273,71.381 RTC.3 28.194,71.381 30.099,69.476 OLED.3
SDA: J2.5 OLED.4 P2.2 RTC.4 | length 101.9
  Top Layer w0.2: J2.5 7.236,25.404 v1(8.89,27.058)
  Bottom Layer w0.2: v1(8.89,27.058) 9.652,27.82 9.652,70.538 10.495,71.381 P2.2 22.606,71.381 25.146,68.841 RTC.4 27.085,68.68 27.974,68.68 28.829,67.825 28.829,57.411 29.21,57.03 31.721,57.03 32.639,57.948 OLED.4
USB_N: D6.2 D6.9 J2.26 J3.2 USB.2 | length 99.7
  Top Layer w0.2: D6.2@9.525,92.717 D6.2@9.525,93.023 ; J3.2 10.017,95.622 9.525,95.13 9.525,93.322 9.517,93.314 D6.2 D6.9 9.517,90.85 7.855,89.187 7.855,85.833 8.016,85.671 USB.2 8.016,83.382 8.133,83.265 8.898,83.265 9.42,82.743 9.42,59.001 18.523,49.898 18.523,41.549 18.685,41.387 v1(18.685,41.306) ; v1(17.656,27.187) 17.656,27.105 17.713,27.048 17.713,26.659 17.823,26.55 17.823,6.352 17.786,6.316 17.786,5.785 J2.26
  Bottom Layer w0.2: v1(17.656,27.187) 17.656,27.268 17.808,27.42 17.808,27.792 17.526,28.074 17.199,28.401 17.199,41.29 17.668,41.759 18.232,41.759 v1(18.685,41.306)
USB_OTG: IC1.4 J2.6 P1.2 | length 90.2
  Top Layer w0.2: P1.2 7.493,71.508 7.493,33.408 9.906,30.995 9.906,25.523 7.736,23.353 J2.6 ; v1(13.843,87.256) 15.077,87.256 IC1.4
  Bottom Layer w0.2: P1.2 6.858,73.794 13.843,80.779 v1(13.843,87.256)
USB_P: D6.4 D6.7 J2.27 J3.3 USB.3 | length 97.8
  Top Layer w0.2: J3.3 8.017,95.495 8.509,95.003 8.509,93.322 8.517,93.314 D6.4 D6.7 8.517,90.312 7.528,89.323 7.528,85.833 7.366,85.671 USB.3 7.375,84.485 7.375,83.561 7.998,82.938 8.763,82.938 9.093,82.608 9.093,58.865 18.196,49.763 18.196,41.525 18.034,41.363 v1(18.034,41.282) ; J2.27 18.186,5.785 18.186,6.316 18.15,6.352 18.15,26.55 18.235,26.635 18.235,27.132 v1(18.288,27.185)
  Bottom Layer w0.2: v1(18.034,41.282) 18.032,41.284 17.655,41.284 17.526,41.155 17.526,28.536 17.757,28.305 18.135,27.927 18.135,27.419 18.288,27.266 v1(18.288,27.185)
VCC: C8.1 OLED.2 P2.1 RTC.5 T1.11 T1.14 U1.2 U1.4 | length 83.8
  Top Layer w0.2: U1.4 19.177,73.667 16.11,76.734 16.11,84.778 18.161,86.829 18.161,101.212 T1.14 22.112,105.163 32.888,105.163 T1.11
  Top Layer w0.5: P2.1 19.156,68.841 U1.4 19.177,66.301 v1(19.304,66.174) 19.177,66.047 U1.2 C8.1
  Bottom Layer w0.5: v1(19.304,66.174) 19.431,66.301 RTC.5 26.924,66.143 27.559,65.508 OLED.2
pads on no net: D6.1 D6.5 D6.6 D6.10 J1.14 J2.MP1 J2.MP2 RTC.2 T1.MH1 T1.MH2 USB. USB.1 USB.4

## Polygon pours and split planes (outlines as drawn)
GND on Bottom Layer "GND_L02_P004" (solid, pour order 4): 0,107.449 0.127,107.576 54.991,107.576 54.991,26.423 54.864,26.55 29.972,26.55 29.972,0 0,0
+5 on Bottom Layer "+5_L02_P003" (solid, pour order 3): 7.239,12.961 0,12.961 0,90.558 18.415,90.558 18.415,85.351 7.239,85.351
GND on Top Layer "GND_L01_P005" (solid, pour order 5): 0,107.576 54.991,107.576 54.991,26.55 29.845,26.55 29.845,0 0,0

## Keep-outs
Keep-Out Layer:
  the board outline again, w1

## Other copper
Top Layer:
  rectangle net +5: 4.826,8.897 6.477,12.199
Bottom Layer:
  rectangle net +5: 4.572,11.183 7.239,14.104
  rectangle net +5: 15.24,86.494 17.78,89.923

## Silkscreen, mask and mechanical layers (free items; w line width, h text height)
Top Overlay:
  lines w1: 25.146,64.523 25.146,78.239 40.386,78.239 40.386,64.523 25.4,64.523 25.146,64.777
  text "GND" at 28.448,75.971 h1.52
  text "GND" at 14.478,75.844 h1.52
  text "DS3231" at 34.163,74.066 h1.52
  text "SCL" at 14.351,73.431 h1.52
  text "SCL" at 28.448,70.891 h1.52
  text "SDA" at 14.351,70.764 h1.52
  text "3.3V" at 14.351,68.351 h1.52
  text "SDA" at 28.448,68.351 h1.52
  text "3.3V" at 28.448,65.811 h1.52
  text "PLACE JUMPER" at 4.808,61.221 h1.52 r90
  text "FOR USB DEVICE" at 6.205,60.586 h1.52 r90
  text "/ eMMC FLASHING" at 7.602,60.324 h1.52 r90
  text "DISCONNECT ALL FROM USB HOST" at 8.999,54.61 h1.52 r90
  text "SCL" at 30.589,54.109 h1.52 r90
  text "3.3V" at 28.049,53.982 h1.52 r90
  text "SDA" at 33.256,53.982 h1.52 r90
  text "GND" at 25.382,53.728 h1.52 r90
  text "All I²C Ports are 3.3V only !" at 15.367,50.035 h2
  text "FPC CONTACT SIDE UP" at 8.001,8.654 h1.52
Document:
  lines w0.003: 8.377,80.084 8.428,80.134 ; 8.844,79.265 8.895,79.315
